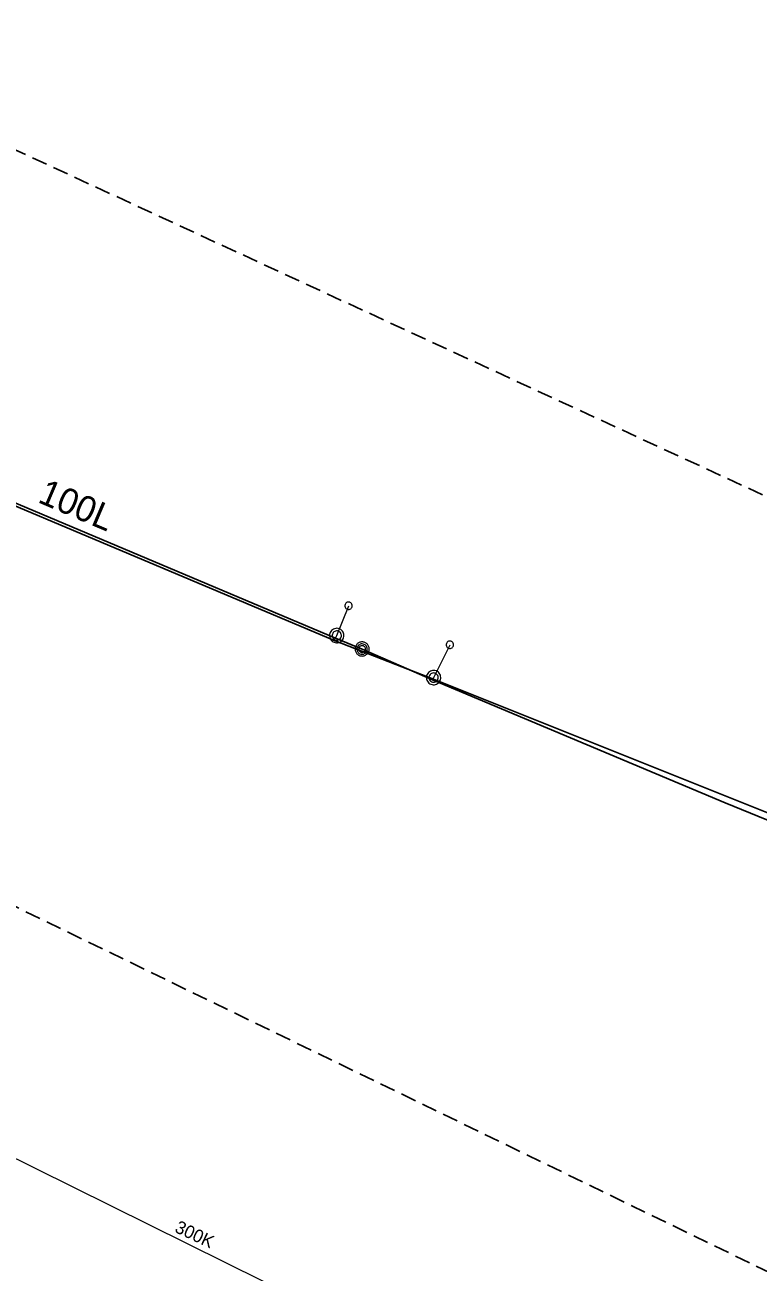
# Model space of a CAD drawing. Extents: x -735085 to -733500, y -1044153 to -1043402.
# Drawn here: x -734758 to -734712.5, y -1043597 to -1043519.6 of the extents above; entities that cross this region are included whole.
import ezdxf

# ---------------------------------------------------------------- set-up
doc = ezdxf.new("R2010")
doc.units = 0
doc.header["$LTSCALE"] = 0.32
doc.linetypes.add('MEDIUM_DASHED', pattern=[4.5, 3, -1.5])
doc.layers.add('15', color=7, linetype='Continuous')
doc.layers.add('16', color=7, linetype='Continuous')
for name, color, linetype, lineweight in [('20', 7, 'Continuous', 13), ('63', 7, 'MEDIUM_DASHED', 25), ('8', 7, 'Continuous', 13)]:
    doc.layers.add(name, color=color, linetype=linetype, lineweight=lineweight)

msp = doc.modelspace()

# ---------------------------------------------------------------- linework, layer by layer
at = {"layer": '20'}
msp.add_line((-734767.879, -1043585.38), (-734722.55, -1043607.8), dxfattribs=at)
msp.add_line((-734767.879, -1043585.38), (-734722.55, -1043607.8), dxfattribs=at)
at = {"layer": '63'}
msp.add_lwpolyline([(-734796.022, -1043808.279), (-734957.658, -1043641.023), (-734957.66, -1043641.021), (-735032.487, -1043496.398), (-735032.488, -1043496.396), (-735032.488, -1043496.394), (-735032.488, -1043496.393), (-735032.488, -1043496.391), (-735014.686, -1043433.916), (-735014.686, -1043433.914), (-735014.685, -1043433.913), (-735014.683, -1043433.911), (-735014.682, -1043433.91), (-735014.68, -1043433.909), (-735014.678, -1043433.909), (-735014.676, -1043433.909), (-734957.569, -1043435.5), (-734957.567, -1043435.5), (-734957.565, -1043435.501), (-734250.468, -1043761.931)], dxfattribs=at)
at = {"layer": '8', "linetype": 'MEDIUM_DASHED', "lineweight": 25}
msp.add_line((-734760.53, -1043573.392), (-734690.747, -1043607.257), dxfattribs=at)
at = {"layer": '8', "lineweight": 25}
for points in [[(-734798.6, -1043532.29), (-734781.989, -1043539.38), (-734773.37, -1043543.03), (-734767.76, -1043545.41), (-734738.719, -1043557.66), (-734737.059, -1043558.35)], [(-734792.71, -1043535.18), (-734782.352, -1043539.852), (-734773.644, -1043543.536), (-734767.807, -1043545.587), (-734738.734, -1043557.836), (-734732.528, -1043560.258), (-734709.46, -1043569.477), (-734674.151, -1043584.087)], [(-734737.059, -1043558.35), (-734732.69, -1043560.26), (-734714.53, -1043567.89), (-734709.92, -1043569.78), (-734695.94, -1043575.82), (-734676.559, -1043583.89)]]:
    msp.add_lwpolyline(points, dxfattribs=at)
at = {"layer": '8'}
for points in [[(-734738.719, -1043557.66), (-734738.629, -1043557.51), (-734737.899, -1043555.66)], [(-734736.629, -1043558.339), (-734736.631, -1043558.294), (-734736.638, -1043558.249), (-734736.65, -1043558.204), (-734736.666, -1043558.162), (-734736.687, -1043558.121), (-734736.712, -1043558.082), (-734736.741, -1043558.047), (-734736.773, -1043558.014), (-734736.809, -1043557.986), (-734736.847, -1043557.961), (-734736.888, -1043557.94), (-734736.931, -1043557.923), (-734736.975, -1043557.911), (-734737.02, -1043557.904), (-734737.066, -1043557.902), (-734737.112, -1043557.904), (-734737.157, -1043557.911), (-734737.201, -1043557.923), (-734737.244, -1043557.94), (-734737.285, -1043557.961), (-734737.323, -1043557.986), (-734737.359, -1043558.014), (-734737.391, -1043558.047), (-734737.42, -1043558.082), (-734737.445, -1043558.121), (-734737.466, -1043558.162), (-734737.482, -1043558.204), (-734737.494, -1043558.249), (-734737.501, -1043558.294), (-734737.504, -1043558.34), (-734737.501, -1043558.385), (-734737.494, -1043558.43), (-734737.482, -1043558.475), (-734737.466, -1043558.517), (-734737.445, -1043558.558), (-734737.42, -1043558.597), (-734737.391, -1043558.632), (-734737.359, -1043558.665), (-734737.323, -1043558.693), (-734737.285, -1043558.718), (-734737.244, -1043558.739), (-734737.201, -1043558.756), (-734737.157, -1043558.767), (-734737.112, -1043558.775), (-734737.066, -1043558.777), (-734737.02, -1043558.775), (-734736.975, -1043558.767), (-734736.931, -1043558.756), (-734736.888, -1043558.739), (-734736.847, -1043558.718), (-734736.809, -1043558.693), (-734736.773, -1043558.665), (-734736.741, -1043558.632), (-734736.712, -1043558.597), (-734736.687, -1043558.558), (-734736.666, -1043558.517), (-734736.65, -1043558.475), (-734736.638, -1043558.43), (-734736.631, -1043558.385), (-734736.629, -1043558.34)], [(-734732.69, -1043560.26), (-734732.62, -1043560.12), (-734731.609, -1043558.08)]]:
    msp.add_lwpolyline(points, dxfattribs=at)
for points in [[(-734737.829, -1043555.439), (-734737.879, -1043555.427), (-734737.933, -1043555.426), (-734737.984, -1043555.437), (-734738.031, -1043555.46), (-734738.072, -1043555.493), (-734738.105, -1043555.535), (-734738.127, -1043555.582), (-734738.139, -1043555.633), (-734738.138, -1043555.685), (-734738.125, -1043555.737), (-734738.1, -1043555.783), (-734738.067, -1043555.823), (-734738.024, -1043555.855), (-734737.977, -1043555.876), (-734737.925, -1043555.886), (-734737.873, -1043555.883), (-734737.822, -1043555.87), (-734737.775, -1043555.844), (-734737.737, -1043555.81), (-734737.706, -1043555.767), (-734737.686, -1043555.718), (-734737.678, -1043555.666), (-734737.682, -1043555.614), (-734737.697, -1043555.563), (-734737.723, -1043555.518), (-734737.759, -1043555.48), (-734737.803, -1043555.451)], [(-734738.484, -1043557.086), (-734738.555, -1043557.067), (-734738.627, -1043557.059), (-734738.7, -1043557.063), (-734738.771, -1043557.08), (-734738.84, -1043557.107), (-734738.902, -1043557.145), (-734738.957, -1043557.193), (-734739.004, -1043557.249), (-734739.041, -1043557.312), (-734739.068, -1043557.381), (-734739.082, -1043557.452), (-734739.085, -1043557.526), (-734739.076, -1043557.597), (-734739.055, -1043557.668), (-734739.023, -1043557.734), (-734738.981, -1043557.793), (-734738.929, -1043557.846), (-734738.87, -1043557.888), (-734738.804, -1043557.921), (-734738.734, -1043557.943), (-734738.662, -1043557.952), (-734738.589, -1043557.95), (-734738.517, -1043557.936), (-734738.448, -1043557.91), (-734738.385, -1043557.874), (-734738.328, -1043557.828), (-734738.28, -1043557.773), (-734738.241, -1043557.711), (-734738.213, -1043557.643), (-734738.196, -1043557.572), (-734738.191, -1043557.499), (-734738.199, -1043557.426), (-734738.217, -1043557.355), (-734738.247, -1043557.289), (-734738.289, -1043557.228), (-734738.338, -1043557.174), (-734738.397, -1043557.13), (-734738.461, -1043557.096)], [(-734738.54, -1043557.237), (-734738.596, -1043557.223), (-734738.655, -1043557.221), (-734738.712, -1043557.229), (-734738.767, -1043557.251), (-734738.817, -1043557.281), (-734738.859, -1043557.323), (-734738.891, -1043557.371), (-734738.914, -1043557.426), (-734738.924, -1043557.483), (-734738.922, -1043557.542), (-734738.909, -1043557.599), (-734738.885, -1043557.652), (-734738.85, -1043557.699), (-734738.806, -1043557.738), (-734738.756, -1043557.767), (-734738.7, -1043557.786), (-734738.642, -1043557.792), (-734738.583, -1043557.787), (-734738.528, -1043557.769), (-734738.476, -1043557.742), (-734738.432, -1043557.703), (-734738.396, -1043557.657), (-734738.37, -1043557.605), (-734738.356, -1043557.548), (-734738.352, -1043557.49), (-734738.362, -1043557.432), (-734738.383, -1043557.377), (-734738.414, -1043557.328), (-734738.455, -1043557.287), (-734738.504, -1043557.254)], [(-734736.742, -1043558.347), (-734736.748, -1043558.286), (-734736.766, -1043558.226), (-734736.795, -1043558.171), (-734736.834, -1043558.123), (-734736.881, -1043558.083), (-734736.935, -1043558.053), (-734736.994, -1043558.033), (-734737.056, -1043558.026), (-734737.118, -1043558.03), (-734737.178, -1043558.046), (-734737.233, -1043558.074), (-734737.283, -1043558.111), (-734737.324, -1043558.158), (-734737.356, -1043558.211), (-734737.376, -1043558.27), (-734737.386, -1043558.331), (-734737.383, -1043558.393), (-734737.368, -1043558.453), (-734737.342, -1043558.51), (-734737.306, -1043558.56), (-734737.26, -1043558.603), (-734737.208, -1043558.635), (-734737.15, -1043558.658), (-734737.089, -1043558.668), (-734737.027, -1043558.667), (-734736.966, -1043558.654), (-734736.909, -1043558.629), (-734736.858, -1043558.594), (-734736.814, -1043558.55), (-734736.78, -1043558.498), (-734736.756, -1043558.441), (-734736.744, -1043558.38)], [(-734736.856, -1043558.347), (-734736.862, -1043558.298), (-734736.879, -1043558.251), (-734736.907, -1043558.21), (-734736.945, -1043558.177), (-734736.989, -1043558.153), (-734737.037, -1043558.141), (-734737.087, -1043558.14), (-734737.135, -1043558.152), (-734737.18, -1043558.174), (-734737.218, -1043558.207), (-734737.247, -1043558.247), (-734737.266, -1043558.294), (-734737.273, -1043558.343), (-734737.268, -1043558.393), (-734737.251, -1043558.44), (-734737.224, -1043558.482), (-734737.187, -1043558.516), (-734737.144, -1043558.54), (-734737.096, -1043558.554), (-734737.046, -1043558.555), (-734736.997, -1043558.545), (-734736.952, -1043558.523), (-734736.913, -1043558.491), (-734736.883, -1043558.452), (-734736.864, -1043558.406), (-734736.856, -1043558.356)], [(-734731.539, -1043557.859), (-734731.59, -1043557.847), (-734731.643, -1043557.846), (-734731.694, -1043557.858), (-734731.742, -1043557.88), (-734731.782, -1043557.913), (-734731.815, -1043557.955), (-734731.837, -1043558.002), (-734731.849, -1043558.053), (-734731.848, -1043558.106), (-734731.835, -1043558.157), (-734731.81, -1043558.204), (-734731.777, -1043558.243), (-734731.734, -1043558.275), (-734731.686, -1043558.296), (-734731.635, -1043558.306), (-734731.583, -1043558.303), (-734731.532, -1043558.29), (-734731.485, -1043558.264), (-734731.447, -1043558.229), (-734731.416, -1043558.186), (-734731.396, -1043558.138), (-734731.388, -1043558.086), (-734731.392, -1043558.033), (-734731.407, -1043557.983), (-734731.434, -1043557.938), (-734731.469, -1043557.899), (-734731.513, -1043557.871)], [(-734732.475, -1043559.696), (-734732.546, -1043559.677), (-734732.619, -1043559.669), (-734732.692, -1043559.673), (-734732.763, -1043559.69), (-734732.831, -1043559.717), (-734732.893, -1043559.755), (-734732.948, -1043559.803), (-734732.995, -1043559.859), (-734733.032, -1043559.922), (-734733.059, -1043559.991), (-734733.073, -1043560.063), (-734733.076, -1043560.136), (-734733.067, -1043560.208), (-734733.046, -1043560.278), (-734733.014, -1043560.344), (-734732.972, -1043560.404), (-734732.919, -1043560.456), (-734732.861, -1043560.499), (-734732.795, -1043560.531), (-734732.725, -1043560.553), (-734732.653, -1043560.562), (-734732.58, -1043560.56), (-734732.507, -1043560.546), (-734732.439, -1043560.52), (-734732.376, -1043560.484), (-734732.319, -1043560.438), (-734732.27, -1043560.383), (-734732.232, -1043560.321), (-734732.204, -1043560.253), (-734732.187, -1043560.181), (-734732.182, -1043560.109), (-734732.19, -1043560.036), (-734732.208, -1043559.965), (-734732.238, -1043559.898), (-734732.28, -1043559.837), (-734732.329, -1043559.784), (-734732.388, -1043559.74), (-734732.452, -1043559.706)], [(-734732.531, -1043559.847), (-734732.587, -1043559.833), (-734732.646, -1043559.831), (-734732.704, -1043559.839), (-734732.758, -1043559.861), (-734732.808, -1043559.892), (-734732.85, -1043559.933), (-734732.882, -1043559.981), (-734732.905, -1043560.036), (-734732.915, -1043560.093), (-734732.913, -1043560.152), (-734732.9, -1043560.209), (-734732.876, -1043560.262), (-734732.841, -1043560.309), (-734732.797, -1043560.348), (-734732.747, -1043560.377), (-734732.691, -1043560.396), (-734732.632, -1043560.402), (-734732.574, -1043560.397), (-734732.518, -1043560.379), (-734732.467, -1043560.351), (-734732.423, -1043560.313), (-734732.387, -1043560.267), (-734732.361, -1043560.214), (-734732.347, -1043560.158), (-734732.343, -1043560.1), (-734732.353, -1043560.042), (-734732.374, -1043559.987), (-734732.405, -1043559.938), (-734732.446, -1043559.896), (-734732.495, -1043559.864)]]:
    msp.add_lwpolyline(points, close=True, dxfattribs=at)

# ---------------------------------------------------------------- texts
at = {"layer": '15'}
msp.add_text('100L', height=1.6, rotation=337, dxfattribs=at).set_placement((-734757.266, -1043549.21))
at = {"layer": '16'}
msp.add_text('300K', height=0.8, rotation=335, dxfattribs=at).set_placement((-734748.756, -1043594.509))

doc.saveas('drawing.dxf')
